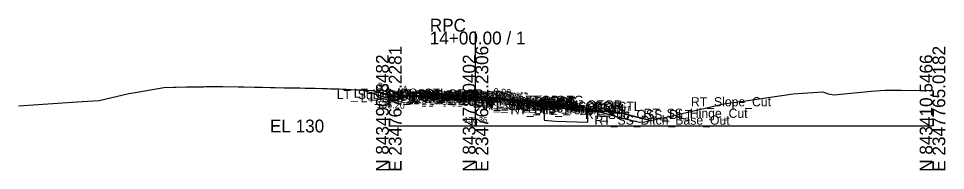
# Model space of a CAD drawing. Extents: x -26 to 203, y -10 to 7538.
# Drawn here: x 0 to 202.8, y 490.3 to 523.4 of the extents above; entities that cross this region are included whole.
import ezdxf

# ---------------------------------------------------------------- set-up
doc = ezdxf.new("R2010")
doc.units = 0
for name, color, linetype in [('Default', 7, 'Continuous'), ('Exist CMT Pavement', 7, 'Continuous'), ('Exist Cross Section Cell', 7, 'Continuous'), ('Exist XS Center Line Elevation Label', 7, 'Continuous'), ('Exist XS Ground Line', 7, 'Continuous'), ('Prop CMT Pvmt Course 1', 7, 'Continuous'), ('Prop CMT Pvmt Course 1 Wedge', 7, 'Continuous'), ('Prop CMT Pvmt Course 2', 7, 'Continuous'), ('Prop CMT Pvmt Course 2 Wedge', 7, 'Continuous'), ('Prop CMT Pvmt Course 3', 7, 'Continuous'), ('Prop CMT Pvmt Course 3 Wedge', 7, 'Continuous'), ('Prop CMT Pvmt Surface', 7, 'Continuous'), ('Prop CMT Pvmt Surface Shoulder', 7, 'Continuous'), ('Prop CMT Pvmt Wedge Surface 1', 7, 'Continuous'), ('Prop CMT Pvmt Wedge Surface 2', 7, 'Continuous'), ('Prop CMT Pvmt Wedge Surface 3', 7, 'Continuous'), ('Prop CMT Shld Paved Course 1', 7, 'Continuous'), ('Prop CMT Shld Paved Course 2', 7, 'Continuous'), ('Prop CMT Shld Paved Course 3', 7, 'Continuous'), ('Prop CMT Slope Grass', 7, 'Continuous'), ('Prop CMT Subgrade Earthwork', 7, 'Continuous'), ('Prop Road Sect_ Recs - UC (Outline)', 7, 'Continuous'), ('Prop Road Sect_ Recs - UEA (pattern)', 7, 'Continuous'), ('Prop XS Earthwork Shape', 7, 'Continuous'), ('Prop XS SE Text', 7, 'Continuous'), ('Prop XS Side Slope Text', 7, 'Continuous'), ('Scratch_Level_0', 7, 'Continuous')]:
    doc.layers.add(name, color=color, linetype=linetype)

msp = doc.modelspace()

# ---------------------------------------------------------------- linework, layer by layer
at = {"layer": 'Exist CMT Pavement'}
for q in [(96, 506.59), (111.17, 505.61)]:
    msp.add_line((100, 506.36), q, dxfattribs=at)
at = {"layer": 'Exist Cross Section Cell'}
for p, q in [((100, 500), (100, 520.6)), ((81.02, 500), (100, 500)), ((100, 500), (200, 500))]:
    msp.add_line(p, q, dxfattribs=at)
at = {"layer": 'Exist XS Ground Line'}
msp.add_lwpolyline([(0, 504.41), (13.96, 505.31), (17.65, 505.58), (24.16, 507.06), (25.99, 507.38), (26.42, 507.45), (31.76, 508.39), (33.88, 508.46), (34.5, 508.47), (36.8, 508.52), (37.89, 508.54), (39.15, 508.57), (40.52, 508.58), (40.94, 508.59), (41.46, 508.59), (42.64, 508.6), (44.25, 508.6), (44.68, 508.6), (48.09, 508.57), (49.3, 508.54), (51.64, 508.49), (53.33, 508.46), (55.16, 508.41), (56.13, 508.4), (58.19, 508.36), (58.57, 508.36), (59.02, 508.35), (60.41, 508.34), (61.56, 508.31), (62.75, 508.29), (63.92, 508.26), (64.93, 508.24), (66.55, 508.2), (67.51, 508.18), (68.32, 508.14), (69.22, 508.11), (70.17, 508.08), (70.98, 508.04), (71.7, 508.01), (72.77, 507.97), (73.88, 507.92), (74.53, 507.89), (75.12, 507.86), (76.28, 507.81), (77.5, 507.76), (79.3, 507.32), (81.88, 506.65), (84.13, 506.26), (87.5, 506.69), (89.91, 506.92), (90.58, 506.84), (92.4, 506.76), (95.11, 506.63), (95.69, 506.6), (96.08, 506.58), (97.54, 506.51), (98.87, 506.42), (100, 506.36), (102.28, 506.23), (102.85, 506.2), (103.48, 506.15), (105.65, 505.99), (107.19, 505.87), (109, 505.74), (110.54, 505.64), (111.17, 505.61), (111.54, 505.55), (112.4, 505.47), (113.45, 505.4), (114.23, 505.37), (115.16, 505.31), (119.67, 504.7), (122.86, 504.27), (132.09, 501.73), (135.92, 500.83), (137.02, 500.91), (140.96, 501.78), (142.08, 502.03), (152.47, 504.4), (154.24, 504.81), (158.55, 505.44), (169.52, 506.99), (171.66, 507.19), (176, 507.44), (177.16, 507.02), (178.46, 506.83), (186.56, 507.6), (189.63, 507.84), (193.13, 507.8), (200, 507.77)], dxfattribs=at)
at = {"layer": 'Prop CMT Pvmt Course 1'}
for p, q in [((100, 506.36), (96, 506.68)), ((96, 506.68), (96, 506.43)), ((96, 506.43), (96, 506.56)), ((96, 506.56), (100, 506.24)), ((96, 506.43), (96, 506.43)), ((100, 506.11), (100, 506.36)), ((100, 506.36), (112, 505.4)), ((100, 506.11), (100, 506.36)), ((100, 506.24), (100, 506.11)), ((111.17, 505.34), (100, 506.24)), ((100, 506.24), (100, 506.11)), ((100, 506.11), (100, 506.11)), ((100, 506.11), (100, 506.11)), ((111.17, 505.22), (111.17, 505.34)), ((112, 505.15), (111.17, 505.22)), ((112, 505.4), (112, 505.15))]:
    msp.add_line(p, q, dxfattribs=at)
at = {"layer": 'Prop CMT Pvmt Course 1 Wedge'}
for q in [(96, 506.56), (111.17, 505.34)]:
    msp.add_line((100, 506.24), q, dxfattribs=at)
at = {"layer": 'Prop CMT Pvmt Course 2'}
for p, q in [((96, 506.1), (96, 506.43)), ((96, 506.43), (96, 506.43)), ((96, 506.43), (96, 506.1)), ((96, 506.1), (96, 506.1)), ((111.17, 504.88), (111.17, 505.22)), ((111.17, 505.22), (112, 505.15)), ((112, 505.15), (112, 504.82)), ((112, 504.82), (111.17, 504.88))]:
    msp.add_line(p, q, dxfattribs=at)
at = {"layer": 'Prop CMT Pvmt Course 2 Wedge'}
for q in [(96, 506.43), (111.17, 505.22)]:
    msp.add_line((100, 506.11), q, dxfattribs=at)
at = {"layer": 'Prop CMT Pvmt Course 3'}
for p, q in [((96, 506.1), (96, 506.1)), ((96, 506.1), (96, 505.76)), ((96, 505.76), (96, 506.1)), ((96, 505.76), (96, 505.76)), ((111.17, 504.88), (112, 504.82)), ((111.17, 504.55), (111.17, 504.88)), ((112, 504.48), (111.17, 504.55)), ((112, 504.82), (112, 504.48))]:
    msp.add_line(p, q, dxfattribs=at)
at = {"layer": 'Prop CMT Pvmt Course 3 Wedge'}
for q in [(96, 506.1), (111.17, 504.88)]:
    msp.add_line((100, 505.78), q, dxfattribs=at)
at = {"layer": 'Prop CMT Pvmt Surface'}
for q in [(96, 506.68), (112, 505.4)]:
    msp.add_line((100, 506.36), q, dxfattribs=at)
at = {"layer": 'Prop CMT Pvmt Surface Shoulder'}
for p, q in [((96, 506.68), (92, 507)), ((112, 505.4), (122, 504.6))]:
    msp.add_line(p, q, dxfattribs=at)
at = {"layer": 'Prop CMT Pvmt Wedge Surface 1'}
for p, q in [((96, 506.43), (96, 506.68)), ((100, 506.24), (96, 506.56)), ((96, 506.56), (96, 506.43)), ((96, 506.43), (96, 506.43)), ((100, 506.24), (111.17, 505.34)), ((111.17, 505.34), (111.17, 505.22)), ((111.17, 505.22), (112, 505.15)), ((112, 505.15), (112, 505.4))]:
    msp.add_line(p, q, dxfattribs=at)
at = {"layer": 'Prop CMT Pvmt Wedge Surface 2'}
for p, q in [((96, 506.43), (96, 506.68)), ((100, 506.11), (96, 506.43)), ((100, 506.11), (112, 505.15)), ((112, 505.15), (112, 505.4))]:
    msp.add_line(p, q, dxfattribs=at)
at = {"layer": 'Prop CMT Pvmt Wedge Surface 3'}
for p, q in [((96, 506.1), (96, 506.68)), ((100, 505.78), (96, 506.1)), ((100, 505.78), (112, 504.82)), ((112, 504.82), (112, 505.4))]:
    msp.add_line(p, q, dxfattribs=at)
at = {"layer": 'Prop CMT Shld Paved Course 1'}
for p, q in [((92, 507), (91.77, 506.77)), ((91.77, 506.77), (96, 506.43)), ((96, 506.68), (92, 507)), ((96, 506.43), (96, 506.68)), ((112, 505.4), (122, 504.6)), ((112, 505.15), (112, 505.4)), ((122.27, 504.33), (112, 505.15)), ((122, 504.6), (122.27, 504.33))]:
    msp.add_line(p, q, dxfattribs=at)
at = {"layer": 'Prop CMT Shld Paved Course 2'}
for p, q in [((91.77, 506.77), (91.46, 506.46)), ((91.46, 506.46), (96, 506.1)), ((96, 506.43), (91.77, 506.77)), ((96, 506.1), (96, 506.43)), ((112, 505.15), (122.27, 504.33)), ((112, 504.82), (112, 505.15)), ((122.63, 503.97), (112, 504.82)), ((122.27, 504.33), (122.63, 503.97))]:
    msp.add_line(p, q, dxfattribs=at)
at = {"layer": 'Prop CMT Shld Paved Course 3'}
for p, q in [((90.96, 506.5), (90.65, 506.19)), ((90.65, 506.19), (96, 505.76)), ((91.46, 506.46), (90.96, 506.5)), ((96, 506.1), (91.46, 506.46)), ((96, 505.76), (96, 506.1)), ((112, 504.82), (122.63, 503.97)), ((112, 504.48), (112, 504.82)), ((123.5, 503.56), (112, 504.48)), ((122.63, 503.97), (123.13, 503.93)), ((123.13, 503.93), (123.5, 503.56))]:
    msp.add_line(p, q, dxfattribs=at)
at = {"layer": 'Prop CMT Slope Grass'}
for p, q in [((82.19, 506.2), (77.5, 507.76)), ((82.19, 506.2), (85.9, 507.12)), ((92, 507), (85.9, 507.12)), ((122, 504.6), (126, 504.28)), ((126, 504.28), (138.33, 501.2))]:
    msp.add_line(p, q, dxfattribs=at)
at = {"layer": 'Prop CMT Subgrade Earthwork'}
for p, q in [((90.65, 506.19), (84.23, 506.71)), ((96, 505.76), (90.65, 506.19)), ((96, 505.76), (96, 506.59)), ((96, 505.76), (96, 505.76)), ((111.17, 504.55), (111.17, 505.61)), ((111.17, 504.55), (112, 504.48)), ((112, 504.48), (123.5, 503.56)), ((123.5, 503.56), (131.39, 502.93))]:
    msp.add_line(p, q, dxfattribs=at)
at = {"layer": 'Prop Road Sect_ Recs - UC (Outline)'}
msp.add_lwpolyline([(115.01, 504.24), (115.01, 501.24), (117.5, 501.04), (124.55, 500.8), (124.49, 503.48)], close=True, dxfattribs=at)
at = {"layer": 'Prop Road Sect_ Recs - UEA (pattern)'}
for p, q in [((81.92, 506.36), (81.92, 506.36)), ((82.66, 506.36), (82.66, 506.36)), ((100, 506.36), (115.87, 505.21)), ((115.87, 505.21), (115.16, 505.31))]:
    msp.add_line(p, q, dxfattribs=at)
msp.add_lwpolyline([(115.16, 505.31), (114.23, 505.37), (113.45, 505.4), (112.4, 505.47), (111.54, 505.55), (111.17, 505.61), (110.54, 505.64), (109, 505.74), (107.19, 505.87), (105.65, 505.99), (103.48, 506.15), (102.85, 506.2), (102.28, 506.23), (100, 506.36)], dxfattribs=at)
at = {"layer": 'Prop XS Earthwork Shape'}
for points in [[(81.92, 506.64), (80.14, 506.2), (75.14, 507.86), (76.28, 507.81), (77.5, 507.76), (79.3, 507.32), (81.88, 506.65)], [(81.92, 506.64), (84.13, 506.26), (86.32, 506.54), (82.68, 506.83)], [(86.32, 506.54), (87.5, 506.69), (89.91, 506.92), (90.58, 506.84), (92.4, 506.76), (95.11, 506.63), (95.69, 506.6), (96, 506.59), (96, 505.76), (90.65, 506.19)], [(96, 506.59), (96.08, 506.58), (97.54, 506.51), (98.87, 506.42), (100, 506.36)], [(100, 506.36), (106.57, 505.92), (105.65, 505.99), (103.48, 506.15), (102.85, 506.2), (102.28, 506.23)], [(106.57, 505.92), (107.19, 505.87), (109, 505.74), (110.54, 505.64), (111.17, 505.61), (111.17, 505.47), (100, 506.36)], [(111.17, 505.47), (112, 505.4), (118.13, 504.91), (115.16, 505.31), (114.23, 505.37), (113.45, 505.4), (112.4, 505.47), (111.54, 505.55), (111.17, 505.61)], [(118.13, 504.91), (119.67, 504.7), (122.86, 504.27), (126.2, 503.35), (123.5, 503.56), (112, 504.48), (111.17, 504.55), (111.17, 505.47), (112, 505.4)], [(126.2, 503.35), (132.09, 501.73), (135.92, 500.83), (137.02, 500.91), (138.33, 501.2), (131.39, 502.93)]]:
    msp.add_lwpolyline(points, close=True, dxfattribs=at)

# ---------------------------------------------------------------- texts
at = {"layer": 'Default'}
msp.add_text('136.20', height=1.5, rotation=358.5679, dxfattribs=at).set_placement((78.39, 503.93))
msp.add_text('-', height=0.0001, dxfattribs=at).set_placement((81.02, 500))
at = {"layer": 'Exist Cross Section Cell'}
for s, p in [('RPC', (90, 520.6)), ('14+00.00 / 1', (90, 517.8)), ('EL 130', (55.02, 498.6))]:
    msp.add_text(s, height=2.8, dxfattribs=at).set_placement(p)
for s, p in [('E 2347677.2281', (83.82, 490)), ('E 2347691.2306', (102.8, 490)), ('E 2347765.0182', (202.8, 490)), ('N 843490.8482', (81.02, 490)), ('N 843478.0402', (100, 490)), ('N 843410.5466', (200, 490))]:
    msp.add_text(s, height=2.8, rotation=90, dxfattribs=at).set_placement(p)
at = {"layer": 'Exist XS Center Line Elevation Label'}
msp.add_text('136.36', height=1.2, dxfattribs=at).set_placement((97.5, 500.76))
at = {"layer": 'Prop XS SE Text'}
msp.add_text('0.08', height=1.5, rotation=355.4261, dxfattribs=at).set_placement((103.87, 506.8))
at = {"layer": 'Prop XS Side Slope Text'}
for s, rotation, p in [('3:1', 339.8789, (78.27, 508.19)), ('4:1', 18.7112, (82.98, 506.65)), ('4:1', 345.9638, (131.11, 503.46))]:
    msp.add_text(s, height=1.5, rotation=rotation, dxfattribs=at).set_placement(p)
at = {"layer": 'Scratch_Level_0'}
for s, p in [('LT_Sub_OSS_DLT', (69.63, 505.87)), ('LT_GS_OS_CTL', (73.37, 506.16)), ('LT_Sub_Trench_Out', (74.86, 505.19)), ('LT_PS3_Shelf_Out', (76.94, 505.5)), ('LT_PV_Sub_Tie_Out', (80.95, 505.59)), ('LT_PS3_OEOP', (81.7, 505.46)), ('LT_PS2_OEOP', (82, 505.77)), ('LT_PS1_OEOP', (82.8, 506)), ('LT_PV_OEEOP_EG', (83.54, 505.59)), ('LT_PV2_OEEOP', (85.31, 505.43)), ('LT_PV3_OEEOP', (85.31, 505.1)), ('LT_PV1_OEEOP', (85.87, 505.56)), ('LT_PV2_OEOT', (86.17, 505.43)), ('LT_PV3_OEOT', (86.17, 505.1)), ('LT_PV1_OEOT', (86.74, 505.68)), ('RT_PV_IEEOP_EG', (88.14, 505.36)), ('LT_PV_IEEOP_EG', (88.19, 505.36)), ('RT_PV2_IEEOP', (89.91, 505.11)), ('LT_PV2_IEEOP', (89.95, 505.11)), ('RT_PV1_IEEOP', (90.47, 505.24)), ('LT_PV1_IEEOP', (90.52, 505.24)), ('PV2_PGL', (93.91, 505.11)), ('PV1_PGL', (94.47, 505.36)), ('LT_Sub_OEEOP', (85.21, 504.76)), ('LT_Sub_OEOT', (86.08, 504.76)), ('RT_PV3_IEEOP', (89.91, 504.78)), ('LT_PV3_IEEOP', (89.95, 504.78)), ('RT_PV_Sub_Tie_Out', (96.07, 504.61)), ('RT_PV_OEEOP_EG', (98.67, 504.61)), ('RT_Sub_OEEOP', (100.34, 503.55)), ('RT_PV2_OEEOP', (100.43, 504.22)), ('RT_PV3_OEEOP', (100.43, 503.88)), ('RT_PV1_OEEOP', (101, 504.34)), ('RT_Sub_OEOT', (102.03, 503.48)), ('RT_PV2_OEOT', (102.13, 504.15)), ('RT_PV3_OEOT', (102.13, 503.82)), ('RT_PV1_OEOT', (102.69, 504.4)), ('RT_PS2_OEOP', (112.46, 503.33)), ('RT_PS1_OEOP', (112.76, 503.6)), ('RT_GS_OS_CTL', (115.32, 503.28)), ('RT_Slope_Cut', (147.13, 504.29)), ('RT_Sub_Trench_Out', (107.65, 502.56)), ('RT_PS3_Shelf_Out', (109.07, 502.93)), ('RT_PS3_OEOP', (112.82, 502.97)), ('RT_Sub_OSS_DLT', (123.93, 501.52)), ('RT_SS_Hinge_Cut', (136.79, 501.78)), ('RT_SS_Ditch_Base_Out', (126.03, 500.28))]:
    msp.add_text(s, height=2, dxfattribs=at).set_placement(p)

doc.saveas('drawing.dxf')
